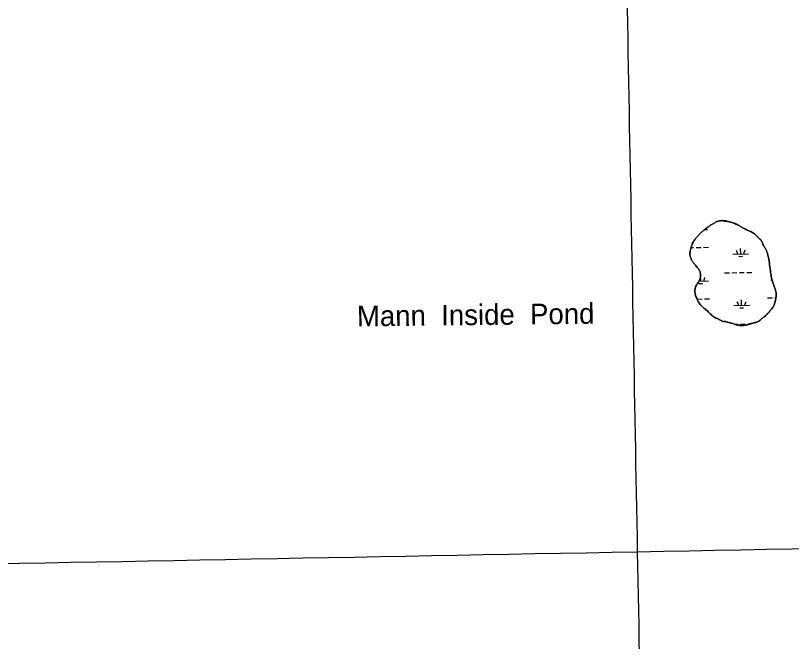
# Model space of a CAD drawing. Extents: x 3957609 to 3995875, y 234277 to 260273.
# Drawn here: x 3963008 to 3968015, y 248308 to 252348 of the extents above; entities that cross this region are included whole.
import ezdxf

# ---------------------------------------------------------------- set-up
doc = ezdxf.new("R2010")
doc.units = 0
for name, color, linetype in [('V-GRID-MAJR', 7, 'Continuous'), ('V-RIVR-IDEN', 7, 'Continuous'), ('V-TOPO-SHOR', 7, 'Continuous'), ('V-WETL-SWMP', 7, 'Continuous')]:
    doc.layers.add(name, color=color, linetype=linetype)

msp = doc.modelspace()

# ---------------------------------------------------------------- linework, layer by layer
at = {"layer": 'V-GRID-MAJR'}
for points in [[(3967193.104, 239799.451), (3967136.284, 242827.44), (3967022.571, 248887.277), (3966908.859, 254947.105), (3966851.966, 257978.948)], [(3961703.892, 248787.859), (3967022.571, 248887.277), (3972341.236, 248987.469), (3977659.886, 249088.434), (3982978.522, 249190.173), (3988297.143, 249292.685), (3993615.748, 249395.971), (3993615.749, 249395.971)]]:
    msp.add_spline(points, degree=3, dxfattribs=at)
at = {"layer": 'V-TOPO-SHOR'}
for points in [[(3967555.694, 251023.328), (3967549.276, 251022.275), (3967545.149, 251021.216), (3967538.731, 251019.705), (3967533.074, 251017.886), (3967529.863, 251016.367), (3967525.429, 251014.391), (3967519.766, 251010.893), (3967514.564, 251007.392), (3967511.963, 251005.717), (3967508.904, 251003.741), (3967504.011, 251001.003), (3967500.644, 250999.026), (3967495.598, 250996.288), (3967490.855, 250993.245), (3967487.948, 250991.725), (3967485.194, 250989.898), (3967481.981, 250987.463), (3967479.224, 250984.873), (3967476.318, 250983.199), (3967469.281, 250978.483), (3967466.066, 250976.048), (3967461.474, 250972.239), (3967458.566, 250969.955), (3967454.433, 250966.453), (3967450.761, 250963.559), (3967448.158, 250961.581), (3967444.332, 250958.535), (3967440.199, 250955.031), (3967437.291, 250952.594), (3967434.535, 250949.852), (3967431.624, 250946.956), (3967427.338, 250942.844), (3967424.581, 250940.101), (3967420.6, 250935.833), (3967417.841, 250932.481), (3967413.399, 250927.91), (3967410.337, 250924.709), (3967405.895, 250919.679), (3967402.832, 250916.175), (3967398.387, 250910.84), (3967395.477, 250907.18), (3967390.881, 250901.54), (3967386.435, 250895.287), (3967383.677, 250891.322), (3967379.841, 250884.613), (3967375.386, 250875.153), (3967373.539, 250869.353), (3967371.075, 250861.11), (3967368.763, 250853.174), (3967367.53, 250848.441), (3967365.683, 250842.182), (3967364.604, 250838.367), (3967363.063, 250833.331), (3967362.14, 250830.126), (3967361.21, 250825.698), (3967360.44, 250822.493), (3967359.664, 250817.453), (3967359.348, 250813.94), (3967359.18, 250807.985), (3967359.477, 250804.317), (3967359.774, 250800.956), (3967360.831, 250796.217), (3967361.894, 250793.313), (3967363.866, 250787.656), (3967365.384, 250783.835), (3967367.354, 250778.176), (3967369.631, 250772.215), (3967370.999, 250769.003), (3967373.736, 250764.109), (3967375.714, 250761.2), (3967378.606, 250756.918), (3967380.889, 250754.01), (3967384.393, 250750.029), (3967386.83, 250747.12), (3967389.419, 250744.212), (3967393.38, 250739.467), (3967395.661, 250736.254), (3967399.469, 250731.203), (3967402.055, 250727.685), (3967405.863, 250722.786), (3967408.3, 250719.419), (3967412.41, 250714.52), (3967415.001, 250711.461), (3967418.957, 250706.103), (3967422.458, 250700.75), (3967424.129, 250697.231), (3967425.8, 250692.951), (3967427.008, 250688.06), (3967428.216, 250682.557), (3967428.665, 250678.738), (3967429.107, 250672.321), (3967428.63, 250664.684), (3967427.85, 250657.66), (3967426.924, 250654.455), (3967425.384, 250649.265), (3967424.002, 250645.908), (3967422.771, 250642.244), (3967420.16, 250636.754), (3967417.548, 250631.261), (3967415.402, 250627.599)], [(3967880.837, 250692.429), (3967880.087, 250698.386), (3967879.184, 250703.887), (3967878.582, 250707.25), (3967877.523, 250711.53), (3967876.921, 250714.891), (3967876.624, 250718.254), (3967875.573, 250726.046), (3967874.975, 250730.783), (3967874.373, 250734.757), (3967873.63, 250742.396), (3967873.187, 250748.812), (3967872.587, 250753.701), (3967872.139, 250757.063), (3967871.537, 250761.188), (3967870.484, 250768.065), (3967869.583, 250773.871), (3967868.375, 250779.372), (3967867.619, 250782.735), (3967866.562, 250787.474), (3967865.051, 250793.739), (3967863.236, 250801.229), (3967862.329, 250804.591), (3967860.965, 250809.943), (3967859.757, 250814.68), (3967858.542, 250817.891), (3967856.873, 250822.477), (3967855.81, 250825.534), (3967853.99, 250829.968), (3967850.799, 250836.698), (3967849.277, 250839.45), (3967847.757, 250842.205), (3967845.476, 250846.182), (3967843.649, 250848.783), (3967841.368, 250852.455), (3967838.173, 250857.503), (3967835.588, 250862.55), (3967834.069, 250866.066), (3967831.337, 250872.491), (3967828.605, 250879.37), (3967827.388, 250882.122), (3967825.715, 250885.029), (3967824.044, 250888.088), (3967821.611, 250892.678), (3967818.719, 250896.809), (3967816.433, 250899.563), (3967813.083, 250903.391), (3967810.646, 250905.994), (3967807.142, 250909.668), (3967804.704, 250912.117), (3967800.893, 250915.794), (3967798.456, 250917.938), (3967795.103, 250921.307), (3967792.818, 250923.605), (3967789.619, 250926.972), (3967785.808, 250930.494), (3967779.408, 250936.161), (3967775.748, 250939.073), (3967769.649, 250943.212), (3967765.379, 250946.127), (3967758.973, 250949.809), (3967752.259, 250953.186), (3967747.836, 250955.029), (3967740.969, 250958.255), (3967736.24, 250960.403), (3967729.221, 250963.477), (3967724.339, 250965.779), (3967717.931, 250969.005), (3967713.661, 250971.307), (3967709.54, 250973.15), (3967703.744, 250976.523), (3967700.082, 250978.52), (3967694.899, 250981.739), (3967691.237, 250983.734), (3967686.508, 250986.802), (3967683.002, 250989.102), (3967677.509, 250992.016), (3967673.544, 250994.318), (3967666.372, 250997.544), (3967659.661, 251000.616), (3967655.387, 251002.459), (3967649.286, 251005.375), (3967645.47, 251007.067), (3967641.809, 251008.603), (3967637.84, 251009.987), (3967632.347, 251012.14), (3967626.088, 251013.987), (3967621.662, 251015.222), (3967614.181, 251016.92), (3967609.448, 251018.001), (3967602.733, 251019.545), (3967598.456, 251020.319), (3967592.654, 251021.403), (3967588.837, 251022.023), (3967583.34, 251022.953), (3967579.83, 251023.42), (3967576.164, 251024.041), (3967570.057, 251024.514), (3967565.932, 251024.524), (3967559.821, 251024.082), (3967555.694, 251023.328)], [(3967765.911, 250362.625), (3967768.969, 250363.532), (3967773.859, 250364.742), (3967777.222, 250365.803), (3967782.113, 250366.86), (3967785.171, 250367.769), (3967789.297, 250368.982), (3967792.201, 250369.891), (3967796.025, 250371.103), (3967800.305, 250372.773), (3967804.283, 250375.208), (3967807.342, 250377.338), (3967812.702, 250382.058), (3967816.22, 250384.952), (3967821.734, 250389.98), (3967824.029, 250391.96), (3967828.009, 250395.157), (3967830.61, 250397.138), (3967833.211, 250398.964), (3967837.19, 250401.703), (3967839.637, 250403.529), (3967842.853, 250406.272), (3967847.907, 250411.3), (3967850.049, 250413.434), (3967854.948, 250417.849), (3967859.542, 250422.269), (3967862.911, 250425.773), (3967865.057, 250428.366), (3967868.579, 250432.021), (3967870.875, 250434.614), (3967873.173, 250437.205), (3967875.319, 250439.795), (3967878.383, 250443.453), (3967882.674, 250448.788), (3967884.972, 250451.686), (3967888.648, 250455.954), (3967892.631, 250460.832), (3967896.465, 250466.626), (3967899.84, 250472.727), (3967901.53, 250476.238), (3967903.529, 250481.425), (3967905.988, 250487.835), (3967908.298, 250495.771), (3967909.378, 250499.13), (3967910.154, 250504.322), (3967911.542, 250509.97), (3967912.622, 250513.786), (3967913.703, 250519.282), (3967914.477, 250523.1), (3967914.948, 250528.292), (3967915.417, 250532.414), (3967916.044, 250538.829), (3967916.361, 250543.256), (3967916.372, 250547.381), (3967916.085, 250554.715), (3967915.485, 250559.603), (3967914.279, 250566.173), (3967912.917, 250570.607), (3967911.098, 250576.723), (3967909.888, 250581.155), (3967907.461, 250588.034), (3967905.945, 250592.926), (3967903.52, 250600.57), (3967901.245, 250607.754), (3967899.424, 250612.493), (3967896.541, 250619.374), (3967894.569, 250625.184), (3967893.203, 250628.855), (3967891.841, 250633.745), (3967890.63, 250638.177), (3967889.873, 250641.081), (3967888.816, 250645.82), (3967887.906, 250648.724), (3967886.85, 250653.31), (3967886.248, 250657.434), (3967885.193, 250662.937), (3967884.437, 250666.757), (3967883.839, 250671.953), (3967883.085, 250675.467), (3967882.027, 250679.594), (3967880.837, 250692.429)], [(3967415.402, 250627.599), (3967412.949, 250624.247), (3967409.119, 250619.215), (3967406.973, 250616.165), (3967403.907, 250611.743), (3967401.451, 250607.625), (3967398.228, 250601.217), (3967395.616, 250595.114), (3967393.765, 250587.786), (3967393.147, 250584.427), (3967392.526, 250581.069), (3967391.75, 250575.877), (3967391.434, 250571.906), (3967391.873, 250563.81), (3967393.075, 250555.71), (3967393.98, 250551.278), (3967395.643, 250544.86), (3967396.702, 250540.58), (3967398.824, 250533.854), (3967401.558, 250527.278), (3967403.532, 250522.69), (3967406.569, 250515.809), (3967411.13, 250507.244), (3967413.106, 250503.267), (3967417.669, 250495.62), (3967419.953, 250491.794), (3967422.234, 250488.734), (3967425.888, 250483.533), (3967428.63, 250480.317), (3967433.201, 250475.723), (3967436.4, 250472.203), (3967441.887, 250467.454), (3967445.239, 250464.543), (3967450.574, 250460.253), (3967453.927, 250457.189), (3967457.738, 250454.125), (3967463.532, 250449.222), (3967469.019, 250444.473), (3967472.371, 250441.104), (3967476.942, 250436.51), (3967480.293, 250433.141), (3967483.646, 250429.621), (3967488.979, 250424.567), (3967494.16, 250419.666), (3967497.666, 250416.448), (3967502.694, 250411.701), (3967505.895, 250409.25), (3967510.622, 250405.266), (3967516.872, 250400.515), (3967520.991, 250398.215), (3967527.706, 250395.753), (3967530.606, 250394.981), (3967534.573, 250393.445), (3967541.135, 250391.137), (3967543.728, 250389.298), (3967547.998, 250386.537), (3967551.201, 250384.544), (3967556.538, 250381.169), (3967560.048, 250379.328), (3967564.777, 250377.024), (3967567.677, 250375.949), (3967573.629, 250373.797), (3967580.043, 250373.016), (3967586.609, 250372.695), (3967590.885, 250372.226), (3967595.159, 250370.839), (3967598.975, 250369.914), (3967605.538, 250367.913), (3967611.492, 250366.522), (3967618.056, 250364.824), (3967622.484, 250363.899), (3967625.537, 250363.278), (3967628.591, 250362.508), (3967635.458, 250360.351), (3967642.937, 250357.736), (3967646.447, 250356.505), (3967651.635, 250354.66), (3967657.435, 250352.813), (3967661.711, 250351.885), (3967668.58, 250350.646), (3967672.705, 250350.177), (3967679.117, 250349.094), (3967682.934, 250348.471), (3967686.445, 250347.853), (3967691.18, 250347.384), (3967699.122, 250347.058), (3967704.621, 250347.349), (3967707.678, 250347.953), (3967713.026, 250348.551), (3967716.54, 250349.305), (3967722.041, 250350.515), (3967727.239, 250351.875), (3967730.907, 250352.631), (3967735.951, 250354.146), (3967739.316, 250355.207), (3967744.053, 250356.415), (3967746.957, 250357.325), (3967752.306, 250358.838), (3967755.976, 250359.899), (3967759.644, 250360.96), (3967765.911, 250362.625)]]:
    msp.add_lwpolyline(points, dxfattribs=at)
at = {"layer": 'V-WETL-SWMP'}
for p, q in [((3967576.954, 251020.07), (3967597.771, 251020.448)), ((3967455.204, 250967.105), (3967473.302, 250967.434)), ((3967400.005, 250850.651), (3967431.999, 250851.232)), ((3967447.997, 250851.523), (3967479.991, 250852.105)), ((3967367.954, 250850.068), (3967384.007, 250850.36)), ((3967637.653, 250808.534), (3967737.637, 250810.352)), ((3967687.645, 250809.443), (3967686.991, 250845.437)), ((3967675.928, 250793.796), (3967699.924, 250794.233)), ((3967429.358, 250633.905), (3967428.76, 250666.758)), ((3967583.002, 250687.449), (3967614.996, 250688.031)), ((3967630.994, 250688.322), (3967662.989, 250688.904)), ((3967678.986, 250689.195), (3967710.981, 250689.777)), ((3967726.978, 250690.067), (3967758.973, 250690.649)), ((3967417.64, 250618.259), (3967441.636, 250618.695)), ((3967418.714, 250633.712), (3967479.35, 250634.814)), ((3967881.191, 250642.121), (3967889.607, 250642.274)), ((3967406.053, 250518.031), (3967438.047, 250518.612)), ((3967454.045, 250518.903), (3967486.039, 250519.485)), ((3967693.693, 250476.823), (3967693.039, 250512.817)), ((3967859.886, 250526.283), (3967891.88, 250526.864)), ((3967907.878, 250527.155), (3967914.857, 250527.282)), ((3967643.702, 250475.914), (3967743.685, 250477.732)), ((3967681.976, 250461.176), (3967705.972, 250461.613)), ((3967648.139, 250355.904), (3967669.037, 250356.284)), ((3967685.034, 250356.575), (3967717.029, 250357.157)), ((3967733.026, 250357.447), (3967748.376, 250357.727))]:
    msp.add_line(p, q, dxfattribs=at)
for points in [[(3967415.402, 250627.6), (3967417.549, 250631.261), (3967420.16, 250636.753), (3967422.77, 250642.245), (3967424.001, 250645.908), (3967425.384, 250649.265), (3967426.925, 250654.455), (3967427.849, 250657.66), (3967428.631, 250664.685), (3967429.108, 250672.321), (3967428.666, 250678.738), (3967428.217, 250682.558), (3967427.009, 250688.06), (3967425.799, 250692.951), (3967424.129, 250697.232), (3967422.458, 250700.749), (3967418.958, 250706.104), (3967415, 250711.46), (3967412.411, 250714.521), (3967408.299, 250719.42), (3967405.863, 250722.786), (3967402.056, 250727.684), (3967399.468, 250731.203), (3967395.662, 250736.254), (3967393.379, 250739.467), (3967389.419, 250744.212), (3967386.83, 250747.121), (3967384.393, 250750.029), (3967380.89, 250754.009), (3967378.606, 250756.917), (3967375.714, 250761.201), (3967373.736, 250764.108), (3967370.999, 250769.003), (3967369.632, 250772.214), (3967367.355, 250778.177), (3967365.384, 250783.834), (3967363.866, 250787.656), (3967361.894, 250793.313), (3967360.832, 250796.218), (3967359.775, 250800.956), (3967359.478, 250804.317), (3967359.181, 250807.984), (3967359.349, 250813.94), (3967359.663, 250817.453), (3967360.439, 250822.492), (3967361.211, 250825.697), (3967362.139, 250830.125), (3967363.063, 250833.33), (3967364.603, 250838.367), (3967365.682, 250842.183), (3967367.53, 250848.441), (3967368.764, 250853.173), (3967371.075, 250861.111), (3967373.54, 250869.353), (3967375.387, 250875.153), (3967379.84, 250884.612), (3967383.676, 250891.323), (3967386.435, 250895.288), (3967390.881, 250901.54), (3967395.477, 250907.18), (3967398.388, 250910.839), (3967402.831, 250916.174), (3967405.895, 250919.679), (3967410.337, 250924.709), (3967413.4, 250927.909), (3967417.841, 250932.481), (3967420.599, 250935.834), (3967424.581, 250940.101), (3967427.338, 250942.844), (3967431.625, 250946.957), (3967434.534, 250949.852), (3967437.291, 250952.595), (3967440.199, 250955.032), (3967444.332, 250958.535), (3967448.158, 250961.58), (3967450.76, 250963.559), (3967454.433, 250966.452), (3967458.566, 250969.955), (3967461.474, 250972.239), (3967466.066, 250976.047), (3967469.28, 250978.483), (3967476.318, 250983.2), (3967479.224, 250984.873), (3967481.98, 250987.463), (3967485.194, 250989.899), (3967487.948, 250991.725), (3967490.854, 250993.245), (3967495.597, 250996.289), (3967500.644, 250999.026), (3967504.01, 251001.003), (3967508.904, 251003.74), (3967511.964, 251005.718), (3967514.565, 251007.392), (3967519.767, 251010.892), (3967525.428, 251014.391), (3967529.862, 251016.366), (3967533.074, 251017.886), (3967538.73, 251019.705), (3967545.149, 251021.216), (3967549.276, 251022.275), (3967555.694, 251023.328)], [(3967555.694, 251023.328), (3967559.82, 251024.082), (3967565.932, 251024.525), (3967570.056, 251024.514), (3967576.165, 251024.041), (3967579.829, 251023.421), (3967583.341, 251022.954), (3967588.838, 251022.024), (3967592.655, 251021.403), (3967598.457, 251020.32), (3967602.732, 251019.545), (3967609.449, 251018.001), (3967614.181, 251016.92), (3967621.662, 251015.221), (3967626.088, 251013.988), (3967632.346, 251012.139), (3967637.84, 251009.987), (3967641.808, 251008.603), (3967645.47, 251007.066), (3967649.285, 251005.376), (3967655.387, 251002.459), (3967659.66, 251000.615), (3967666.373, 250997.544), (3967673.544, 250994.318), (3967677.51, 250992.017), (3967683.002, 250989.101), (3967686.509, 250986.801), (3967691.237, 250983.734), (3967694.898, 250981.739), (3967700.083, 250978.519), (3967703.744, 250976.524), (3967709.54, 250973.149), (3967713.66, 250971.306), (3967717.931, 250969.004), (3967724.339, 250965.78), (3967729.221, 250963.477), (3967736.24, 250960.404), (3967740.969, 250958.254), (3967747.835, 250955.029), (3967752.26, 250953.185), (3967758.973, 250949.808), (3967765.379, 250946.126), (3967769.649, 250943.213), (3967775.748, 250939.074), (3967779.407, 250936.162), (3967785.808, 250930.495), (3967789.618, 250926.972), (3967792.818, 250923.604), (3967795.103, 250921.307), (3967798.455, 250917.938), (3967800.894, 250915.793), (3967804.704, 250912.118), (3967807.141, 250909.668), (3967810.645, 250905.993), (3967813.083, 250903.39), (3967816.434, 250899.563), (3967818.718, 250896.808), (3967821.61, 250892.677), (3967824.043, 250888.088), (3967825.715, 250885.029), (3967827.388, 250882.123), (3967828.604, 250879.37), (3967831.336, 250872.49), (3967834.069, 250866.067), (3967835.588, 250862.55), (3967838.172, 250857.503), (3967841.367, 250852.455), (3967843.649, 250848.783), (3967845.476, 250846.182), (3967847.757, 250842.204), (3967849.278, 250839.451), (3967850.799, 250836.698), (3967853.99, 250829.969), (3967855.811, 250825.535), (3967856.873, 250822.477), (3967858.542, 250817.891), (3967859.756, 250814.68), (3967860.966, 250809.942), (3967862.328, 250804.592), (3967863.236, 250801.229), (3967865.05, 250793.74), (3967866.562, 250787.474), (3967867.619, 250782.736), (3967868.375, 250779.373), (3967869.583, 250773.871), (3967870.485, 250768.065), (3967871.537, 250761.188), (3967872.138, 250757.063), (3967872.588, 250753.701), (3967873.187, 250748.812), (3967873.629, 250742.395), (3967874.373, 250734.756), (3967874.975, 250730.783), (3967875.574, 250726.046), (3967876.624, 250718.253), (3967876.921, 250714.892), (3967877.523, 250711.53), (3967878.582, 250707.25), (3967879.185, 250703.888), (3967880.087, 250698.387), (3967880.836, 250692.428)], [(3967880.836, 250692.428), (3967882.026, 250679.594), (3967883.085, 250675.467), (3967883.84, 250671.952), (3967884.438, 250666.757), (3967885.193, 250662.937), (3967886.248, 250657.435), (3967886.849, 250653.31), (3967887.907, 250648.724), (3967888.816, 250645.82), (3967889.873, 250641.082), (3967890.63, 250638.178), (3967891.841, 250633.745), (3967893.203, 250628.854), (3967894.569, 250625.184), (3967896.54, 250619.375), (3967899.425, 250612.494), (3967901.246, 250607.754), (3967903.52, 250600.57), (3967905.945, 250592.926), (3967907.46, 250588.034), (3967909.887, 250581.155), (3967911.098, 250576.722), (3967912.916, 250570.607), (3967914.279, 250566.174), (3967915.485, 250559.603), (3967916.084, 250554.714), (3967916.371, 250547.381), (3967916.361, 250543.257), (3967916.044, 250538.828), (3967915.417, 250532.414), (3967914.949, 250528.291), (3967914.478, 250523.099), (3967913.704, 250519.282), (3967912.621, 250513.786), (3967911.543, 250509.97), (3967910.154, 250504.321), (3967909.377, 250499.13), (3967908.299, 250495.772), (3967905.988, 250487.835), (3967903.529, 250481.426), (3967901.53, 250476.237), (3967899.841, 250472.728), (3967896.465, 250466.626), (3967892.632, 250460.832), (3967888.648, 250455.954), (3967884.972, 250451.686), (3967882.673, 250448.789), (3967878.383, 250443.454), (3967875.319, 250439.795), (3967873.174, 250437.204), (3967870.876, 250434.613), (3967868.579, 250432.022), (3967865.056, 250428.365), (3967862.911, 250425.773), (3967859.542, 250422.269), (3967854.949, 250417.85), (3967850.05, 250413.433), (3967847.906, 250411.3), (3967842.853, 250406.271), (3967839.638, 250403.53), (3967837.19, 250401.703), (3967833.211, 250398.964), (3967830.61, 250397.137), (3967828.009, 250395.158), (3967824.029, 250391.96), (3967821.733, 250389.98), (3967816.221, 250384.953), (3967812.701, 250382.059), (3967807.343, 250377.338), (3967804.283, 250375.207), (3967800.305, 250372.773), (3967796.024, 250371.103), (3967792.202, 250369.891), (3967789.298, 250368.981), (3967785.171, 250367.77), (3967782.113, 250366.861), (3967777.223, 250365.804), (3967773.86, 250364.743), (3967768.969, 250363.533), (3967765.911, 250362.624), (3967759.645, 250360.96), (3967755.976, 250359.899), (3967752.307, 250358.839), (3967746.957, 250357.325), (3967744.053, 250356.416), (3967739.315, 250355.206), (3967735.952, 250354.145), (3967730.907, 250352.63), (3967727.239, 250351.875), (3967722.042, 250350.514), (3967716.54, 250349.305), (3967713.025, 250348.55), (3967707.678, 250347.953), (3967704.621, 250347.349), (3967699.121, 250347.057), (3967691.179, 250347.383), (3967686.445, 250347.853), (3967682.934, 250348.472), (3967679.116, 250349.093), (3967672.704, 250350.178)], [(3967672.704, 250350.178), (3967668.581, 250350.647), (3967661.71, 250351.886), (3967657.435, 250352.813), (3967651.635, 250354.66), (3967646.447, 250356.506), (3967642.936, 250357.737), (3967635.458, 250360.352), (3967628.59, 250362.508), (3967625.537, 250363.279), (3967622.483, 250363.898), (3967618.056, 250364.825), (3967611.492, 250366.522), (3967605.538, 250367.912), (3967598.975, 250369.914), (3967595.159, 250370.84), (3967590.885, 250372.225), (3967586.609, 250372.694), (3967580.042, 250373.016), (3967573.628, 250373.796), (3967567.677, 250375.949), (3967564.777, 250377.025), (3967560.048, 250379.328), (3967556.539, 250381.17), (3967551.201, 250384.544), (3967547.998, 250386.537), (3967543.728, 250389.298), (3967541.136, 250391.137), (3967534.574, 250393.445), (3967530.606, 250394.982), (3967527.706, 250395.753), (3967520.991, 250398.214), (3967516.872, 250400.515), (3967510.622, 250405.266), (3967505.896, 250409.249), (3967502.695, 250411.701), (3967497.666, 250416.449), (3967494.161, 250419.665), (3967488.979, 250424.566), (3967483.646, 250429.62), (3967480.294, 250433.142), (3967476.942, 250436.511), (3967472.371, 250441.104), (3967469.019, 250444.473), (3967463.532, 250449.222), (3967457.739, 250454.125), (3967453.928, 250457.189), (3967450.575, 250460.252), (3967445.24, 250464.543), (3967441.887, 250467.453), (3967436.4, 250472.202), (3967433.201, 250475.723), (3967428.63, 250480.317), (3967425.888, 250483.532), (3967422.235, 250488.734), (3967419.952, 250491.795), (3967417.67, 250495.619), (3967413.106, 250503.268), (3967411.131, 250507.244), (3967406.569, 250515.81), (3967403.532, 250522.691), (3967401.557, 250527.278), (3967398.824, 250533.853), (3967396.702, 250540.58), (3967395.644, 250544.859), (3967393.98, 250551.279), (3967393.074, 250555.711), (3967391.872, 250563.81), (3967391.434, 250571.906), (3967391.75, 250575.877), (3967392.526, 250581.069), (3967393.146, 250584.427), (3967393.765, 250587.786), (3967395.616, 250595.114), (3967398.228, 250601.217), (3967401.452, 250607.625), (3967403.906, 250611.743), (3967406.972, 250616.165), (3967409.118, 250619.214), (3967412.949, 250624.246), (3967415.402, 250627.6)]]:
    msp.add_lwpolyline(points, dxfattribs=at)
for centre, start, end in [((3967632.403, 250808.913), 0.269879, 41.813537), ((3967742.87, 250810.922), 140.269876, 181.813534), ((3967484.583, 250635.384), 140.269876, 181.813534), ((3967748.918, 250478.302), 140.269876, 181.813534), ((3967638.451, 250476.293), 0.269879, 41.813537)]:
    msp.add_arc(centre, 35.246, start, end, dxfattribs=at)

# ---------------------------------------------------------------- texts
at = {"layer": 'V-RIVR-IDEN'}
msp.add_text('Mann  Inside  Pond', height=132.99974, rotation=0.658314, dxfattribs=at).set_placement((3965211.894, 250341.245))

doc.saveas('drawing.dxf')
